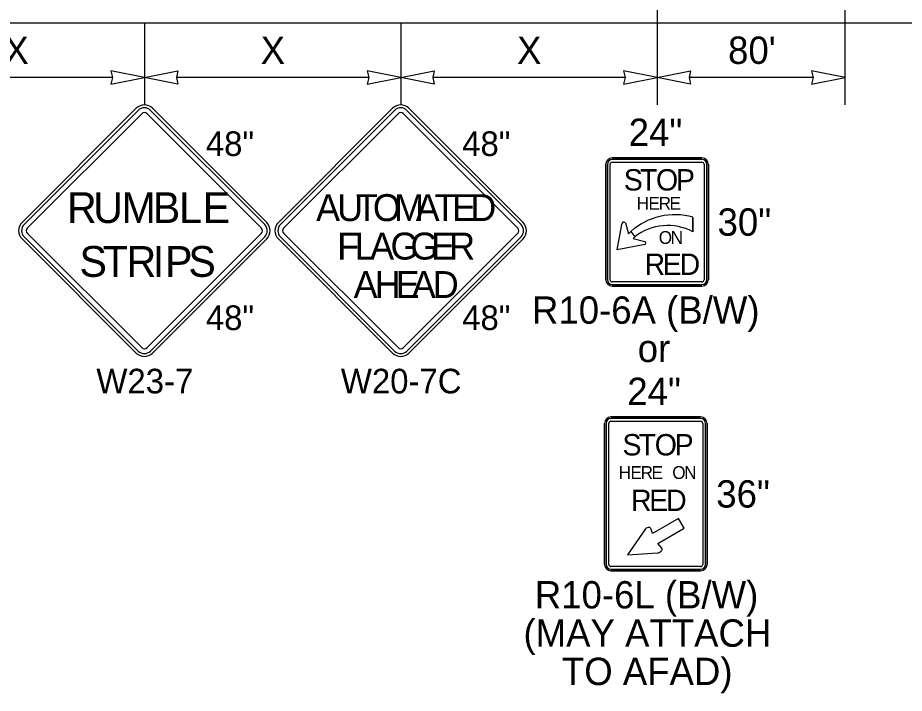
# Model space of a CAD drawing. Extents: x 99999.1 to 100095.7, y 99995 to 100010.7.
# Drawn here: x 100042.406 to 100045, y 100003.772 to 100005.747 of the extents above; entities that cross this region are included whole.
import ezdxf

# ---------------------------------------------------------------- set-up
doc = ezdxf.new("R2010")
doc.units = 0
for name, color, linetype in [('RD_ED_ShoulderPavedEdge', 7, 'Continuous'), ('TR_SN_ConstructionSigns', 7, 'Continuous'), ('TR_WZ_WorkZoneDetails', 7, 'Continuous'), ('TR_WZ_WorkZoneTextCurrent', 7, 'Continuous')]:
    doc.layers.add(name, color=color, linetype=linetype)

msp = doc.modelspace()

# ---------------------------------------------------------------- linework, layer by layer
at = {"layer": 'RD_ED_ShoulderPavedEdge'}
msp.add_line((100040.1076, 100005.7323), (100055.6424, 100005.7323), dxfattribs=at)
at = {"layer": 'TR_SN_ConstructionSigns'}
for p, q in [((100042.7528, 100005.4824), (100042.4187, 100005.1483)), ((100042.7588, 100005.4765), (100042.4246, 100005.1424)), ((100043.1287, 100005.1424), (100042.7945, 100005.4765)), ((100043.1346, 100005.1483), (100042.8005, 100005.4824)), ((100043.5028, 100005.4824), (100043.1687, 100005.1483)), ((100043.5088, 100005.4765), (100043.1746, 100005.1424)), ((100043.8787, 100005.1424), (100043.5445, 100005.4765)), ((100043.8846, 100005.1483), (100043.5505, 100005.4824)), ((100042.4346, 100005.1324), (100042.7687, 100005.4665)), ((100042.7846, 100005.4665), (100043.1187, 100005.1324)), ((100043.1846, 100005.1324), (100043.5187, 100005.4665)), ((100043.5346, 100005.4665), (100043.8687, 100005.1324)), ((100044.1267, 100005.3186), (100044.1267, 100004.9811)), ((100044.1267, 100004.9811), (100044.1267, 100005.3186)), ((100044.1267, 100005.3186), (100044.1267, 100004.9811)), ((100044.1267, 100004.9811), (100044.1267, 100005.3186)), ((100044.1313, 100005.3186), (100044.1313, 100004.9811)), ((100044.1392, 100004.9811), (100044.1392, 100005.3186)), ((100044.4079, 100005.3373), (100044.1454, 100005.3373)), ((100044.1454, 100005.3373), (100044.4079, 100005.3373)), ((100044.4079, 100005.3373), (100044.1454, 100005.3373)), ((100044.1454, 100005.3373), (100044.4079, 100005.3373)), ((100044.4079, 100005.3326), (100044.1454, 100005.3326)), ((100044.1454, 100005.3248), (100044.4079, 100005.3248)), ((100044.4142, 100005.3186), (100044.4142, 100004.9811)), ((100044.422, 100004.9811), (100044.422, 100005.3186)), ((100044.4267, 100004.9811), (100044.4267, 100005.3186)), ((100044.4267, 100005.3186), (100044.4267, 100004.9811)), ((100044.4267, 100004.9811), (100044.4267, 100005.3186)), ((100044.4267, 100005.3186), (100044.4267, 100004.9811)), ((100044.3816, 100005.1635), (100044.3813, 100005.1216)), ((100044.3813, 100005.1216), (100044.3816, 100005.1635)), ((100044.1595, 100005.0686), (100044.1731, 100005.143)), ((100044.1839, 100005.1479), (100044.1933, 100005.1154)), ((100042.7687, 100004.7824), (100042.4346, 100005.1165)), ((100043.1187, 100005.1165), (100042.7846, 100004.7824)), ((100043.5187, 100004.7824), (100043.1846, 100005.1165)), ((100043.8687, 100005.1165), (100043.5346, 100004.7824)), ((100044.1933, 100005.1154), (100044.1996, 100005.1218)), ((100044.1996, 100005.1218), (100044.2113, 100005.1069)), ((100044.1996, 100005.1218), (100044.2113, 100005.1069)), ((100042.4187, 100005.1006), (100042.7528, 100004.7665)), ((100042.4246, 100005.1066), (100042.7588, 100004.7725)), ((100042.7945, 100004.7725), (100043.1287, 100005.1066)), ((100042.8005, 100004.7665), (100043.1346, 100005.1006)), ((100043.1687, 100005.1006), (100043.5028, 100004.7665)), ((100043.1746, 100005.1066), (100043.5088, 100004.7725)), ((100043.5445, 100004.7725), (100043.8787, 100005.1066)), ((100043.5505, 100004.7665), (100043.8846, 100005.1006)), ((100044.2406, 100005.0837), (100044.1595, 100005.0686)), ((100044.2113, 100005.1069), (100044.2066, 100005.1021)), ((100044.2066, 100005.1021), (100044.2408, 100005.0929)), ((100044.4079, 100004.9748), (100044.1454, 100004.9748)), ((100044.1454, 100004.967), (100044.4079, 100004.967)), ((100044.1454, 100004.9623), (100044.4079, 100004.9623)), ((100044.4079, 100004.9623), (100044.1454, 100004.9623)), ((100044.1454, 100004.9623), (100044.4079, 100004.9623)), ((100044.4079, 100004.9623), (100044.1454, 100004.9623)), ((100044.4041, 100004.5796), (100044.1416, 100004.5796)), ((100044.1416, 100004.5796), (100044.4041, 100004.5796)), ((100044.4041, 100004.5796), (100044.1416, 100004.5796)), ((100044.4041, 100004.5749), (100044.1416, 100004.5749)), ((100044.1416, 100004.5671), (100044.4041, 100004.5671)), ((100044.1229, 100004.5609), (100044.1229, 100004.1484)), ((100044.1229, 100004.1484), (100044.1229, 100004.5609)), ((100044.1229, 100004.5609), (100044.1229, 100004.1484)), ((100044.1276, 100004.5609), (100044.1276, 100004.1484)), ((100044.1354, 100004.1484), (100044.1354, 100004.5609)), ((100044.4104, 100004.5609), (100044.4104, 100004.1484)), ((100044.4182, 100004.1484), (100044.4182, 100004.5609)), ((100044.4229, 100004.1484), (100044.4229, 100004.5609)), ((100044.4229, 100004.5609), (100044.4229, 100004.1484)), ((100044.4229, 100004.1484), (100044.4229, 100004.5609)), ((100044.3396, 100004.2827), (100044.263, 100004.2385)), ((100044.356, 100004.2543), (100044.3396, 100004.2827)), ((100044.2786, 100004.2096), (100044.356, 100004.2543)), ((100044.2424, 100004.2523), (100044.1898, 100004.1766)), ((100044.263, 100004.2385), (100044.2592, 100004.2511)), ((100044.2909, 100004.1959), (100044.2786, 100004.2096)), ((100044.1898, 100004.1766), (100044.2776, 100004.1827)), ((100044.4041, 100004.1421), (100044.1416, 100004.1421)), ((100044.1416, 100004.1343), (100044.4041, 100004.1343)), ((100044.1416, 100004.1296), (100044.4041, 100004.1296)), ((100044.4041, 100004.1296), (100044.1416, 100004.1296)), ((100044.1416, 100004.1296), (100044.4041, 100004.1296))]:
    msp.add_line(p, q, dxfattribs=at)
for centre, radius, start, end in [((100042.7767, 100005.4586), 0.0338, 45, 135), ((100042.7767, 100005.4586), 0.0253, 45, 135), ((100043.5267, 100005.4586), 0.0338, 45, 135), ((100043.5267, 100005.4586), 0.0253, 45, 135), ((100042.7767, 100005.4586), 0.0113, 45, 135), ((100043.5267, 100005.4586), 0.0113, 45, 135), ((100044.1454, 100005.3186), 0.0187, 90, 180), ((100044.1454, 100005.3186), 0.0187, 90, 180), ((100044.1454, 100005.3186), 0.0187, 90, 180), ((100044.1454, 100005.3186), 0.0187, 90, 180), ((100044.1454, 100005.3186), 0.0141, 90, 180), ((100044.1454, 100005.3186), 0.00625, 90, 180), ((100044.4079, 100005.3186), 0.0187, 0, 90), ((100044.4079, 100005.3186), 0.0187, 0, 90), ((100044.4079, 100005.3186), 0.0187, 0, 90), ((100044.4079, 100005.3186), 0.0187, 0, 90), ((100044.4079, 100005.3186), 0.0141, 0, 90), ((100044.4079, 100005.3186), 0.00625, 0, 90), ((100044.3279, 100004.9804), 0.1909, 73.6434, 132.2131), ((100044.3279, 100004.9804), 0.1909, 73.6434, 132.2131), ((100042.4425, 100005.1245), 0.0338, 135, 225), ((100042.4425, 100005.1245), 0.0253, 135, 225), ((100043.1108, 100005.1245), 0.0253, 315, 45), ((100043.1108, 100005.1245), 0.0338, 315, 45), ((100043.1925, 100005.1245), 0.0338, 135, 225), ((100043.1925, 100005.1245), 0.0253, 135, 225), ((100043.8608, 100005.1245), 0.0253, 315, 45), ((100043.8608, 100005.1245), 0.0338, 315, 45), ((100044.3078, 100004.981), 0.1586, 62.4149, 127.4769), ((100044.3078, 100004.981), 0.1586, 62.4149, 127.4769), ((100042.4425, 100005.1245), 0.0113, 135, 225), ((100043.1108, 100005.1245), 0.0113, 315, 45), ((100043.1925, 100005.1245), 0.0113, 135, 225), ((100043.8608, 100005.1245), 0.0113, 315, 45), ((100044.1454, 100004.9811), 0.0187, 180, 270), ((100044.1454, 100004.9811), 0.0187, 180, 270), ((100044.1454, 100004.9811), 0.0187, 180, 270), ((100044.1454, 100004.9811), 0.0187, 180, 270), ((100044.1454, 100004.9811), 0.0141, 180, 270), ((100044.1454, 100004.9811), 0.00625, 180, 270), ((100044.4079, 100004.9811), 0.0187, 270, 0), ((100044.4079, 100004.9811), 0.0187, 270, 0), ((100044.4079, 100004.9811), 0.0187, 270, 0), ((100044.4079, 100004.9811), 0.0141, 270, 0), ((100044.4079, 100004.9811), 0.00625, 270, 0), ((100044.4079, 100004.9811), 0.0187, 270, 0), ((100042.7767, 100004.7904), 0.0253, 225, 315), ((100042.7767, 100004.7904), 0.0113, 225, 315), ((100043.5267, 100004.7904), 0.0253, 225, 315), ((100043.5267, 100004.7904), 0.0113, 225, 315), ((100042.7767, 100004.7904), 0.0338, 225, 315), ((100043.5267, 100004.7904), 0.0338, 225, 315), ((100044.1416, 100004.5609), 0.0187, 90, 180), ((100044.1416, 100004.5609), 0.0187, 90, 180), ((100044.1416, 100004.5609), 0.0187, 90, 180), ((100044.1416, 100004.5609), 0.0141, 90, 180), ((100044.1416, 100004.5609), 0.00625, 90, 180), ((100044.4041, 100004.5609), 0.0187, 0, 90), ((100044.4041, 100004.5609), 0.0187, 0, 90), ((100044.4041, 100004.5609), 0.0187, 0, 90), ((100044.4041, 100004.5609), 0.0141, 0, 90), ((100044.4041, 100004.5609), 0.00625, 0, 90), ((100044.1416, 100004.1484), 0.0187, 180, 270), ((100044.1416, 100004.1484), 0.0187, 180, 270), ((100044.1416, 100004.1484), 0.0187, 180, 270), ((100044.1416, 100004.1484), 0.0141, 180, 270), ((100044.1416, 100004.1484), 0.00625, 180, 270), ((100044.4041, 100004.1484), 0.0187, 270, 0), ((100044.4041, 100004.1484), 0.0187, 270, 0), ((100044.4041, 100004.1484), 0.0187, 270, 0), ((100044.4041, 100004.1484), 0.0141, 270, 0), ((100044.4041, 100004.1484), 0.00625, 270, 0)]:
    msp.add_arc(centre, radius, start, end, dxfattribs=at)
for centre, major_axis, ratio, start_param, end_param in [((100044.1795, 100005.1431), (-0.00647, -0.00009), 0.989437, 3.962549, 6.283185), ((100044.2384, 100005.0883), (-0.0046, 0.00239), 0.999053, 2.490568, 4.712389), ((100044.2492, 100004.248), (0.00934, 0.00539), 0.700347, 5.977036, 8.198856), ((100044.2816, 100004.1909), (-0.00913, -0.00527), 0.700347, 0.771965, 3.092601)]:
    msp.add_ellipse(centre, major_axis=major_axis, ratio=ratio, start_param=start_param, end_param=end_param, dxfattribs=at)
at = {"layer": 'TR_WZ_WorkZoneDetails'}
for p, q in [((100044.2767, 100008.7991), (100044.2767, 100005.4923)), ((100044.8267, 100005.4923), (100044.8267, 100007.7323)), ((100042.7767, 100005.7323), (100042.7767, 100005.4923)), ((100043.5267, 100005.7323), (100043.5267, 100005.4923)), ((100042.6829, 100005.5723), (100042.1204, 100005.5723)), ((100043.4329, 100005.5723), (100042.8704, 100005.5723)), ((100044.1829, 100005.5723), (100043.6204, 100005.5723)), ((100044.7329, 100005.5723), (100044.3704, 100005.5723))]:
    msp.add_line(p, q, dxfattribs=at)
for points in [[(100042.7767, 100005.5723), (100042.6784, 100005.5916), (100042.6829, 100005.5723), (100042.6784, 100005.5531)], [(100042.7767, 100005.5723), (100042.8749, 100005.5916), (100042.8704, 100005.5723), (100042.8749, 100005.5531)], [(100043.5267, 100005.5723), (100043.4284, 100005.5916), (100043.4329, 100005.5723), (100043.4284, 100005.5531)], [(100043.5267, 100005.5723), (100043.6249, 100005.5916), (100043.6204, 100005.5723), (100043.6249, 100005.5531)], [(100044.2767, 100005.5723), (100044.1784, 100005.5916), (100044.1829, 100005.5723), (100044.1784, 100005.5531)], [(100044.2767, 100005.5723), (100044.3749, 100005.5916), (100044.3704, 100005.5723), (100044.3749, 100005.5531)], [(100044.8267, 100005.5723), (100044.7284, 100005.5916), (100044.7329, 100005.5723), (100044.7284, 100005.5531)]]:
    msp.add_lwpolyline(points, close=True, dxfattribs=at)

# ---------------------------------------------------------------- texts
at = {"layer": 'TR_SN_ConstructionSigns'}
for s, height, p in [('24"', 0.08, (100044.1936, 100005.3723)), ('48"', 0.072, (100042.9564, 100005.343)), ('48"', 0.072, (100043.7064, 100005.343)), ('30"', 0.08, (100044.4536, 100005.1098)), ('R10-6A (B/W)', 0.08, (100043.9107, 100004.8523)), ('48"', 0.072, (100042.9564, 100004.8339)), ('48"', 0.072, (100043.7064, 100004.8339)), ('or', 0.08, (100044.2201, 100004.7403)), ('W23-7', 0.072, (100042.6361, 100004.6486)), ('W20-7C', 0.072, (100043.3514, 100004.6486)), ('24"', 0.08, (100044.1895, 100004.6146)), ('36"', 0.08, (100044.4498, 100004.3146)), ('R10-6L (B/W)', 0.08, (100043.919, 100004.0196)), ('(MAY ATTACH', 0.08, (100043.8858, 100003.9076)), ('TO AFAD)', 0.08, (100043.9982, 100003.7956))]:
    msp.add_text(s, height=height, rotation=360, dxfattribs=at).set_placement(p)
for s, height, p in [('S', 0.0625, (100044.1792, 100005.242)), ('T', 0.0625, (100044.2267, 100005.242)), ('O', 0.0625, (100044.2735, 100005.242)), ('P', 0.0625, (100044.3317, 100005.242)), ('R', 0.09, (100042.5503, 100005.147)), ('U', 0.09, (100042.6268, 100005.147)), ('M', 0.09, (100042.7096, 100005.147)), ('B', 0.09, (100042.8014, 100005.147)), ('L', 0.09, (100042.8779, 100005.147)), ('E', 0.09, (100042.9472, 100005.147)), ('A', 0.0787, (100043.279, 100005.1526)), ('U', 0.0787, (100043.3404, 100005.1526)), ('T', 0.0787, (100043.3955, 100005.1526)), ('O', 0.0787, (100043.4451, 100005.1526)), ('M', 0.0787, (100043.5074, 100005.1526)), ('A', 0.0787, (100043.5704, 100005.1526)), ('T', 0.0787, (100043.6255, 100005.1526)), ('E', 0.0787, (100043.6767, 100005.1526)), ('D', 0.0787, (100043.7302, 100005.1526)), ('H', 0.0375, (100044.217, 100005.1858)), ('E', 0.0375, (100044.2515, 100005.1858)), ('R', 0.0375, (100044.2812, 100005.1858)), ('E', 0.0375, (100044.313, 100005.1858)), ('F', 0.0787, (100043.3408, 100005.0401)), ('L', 0.0787, (100043.392, 100005.0401)), ('A', 0.0787, (100043.4369, 100005.0401)), ('G', 0.0787, (100043.4967, 100005.0401)), ('G', 0.0787, (100043.555, 100005.0401)), ('E', 0.0787, (100043.6149, 100005.0401)), ('R', 0.0787, (100043.6684, 100005.0401)), ('O', 0.0375, (100044.2815, 100005.0858)), ('N', 0.0375, (100044.3164, 100005.0858)), ('S', 0.09, (100042.5868, 100004.9895)), ('T', 0.09, (100042.6552, 100004.9895)), ('R', 0.09, (100042.7245, 100004.9895)), ('I', 0.09, (100042.801, 100004.9895)), ('P', 0.09, (100042.837, 100004.9895)), ('S', 0.09, (100042.9054, 100004.9895)), ('R', 0.0625, (100044.2399, 100004.9951)), ('E', 0.0625, (100044.293, 100004.9951)), ('D', 0.0625, (100044.3424, 100004.9951)), ('A', 0.0787, (100043.3888, 100004.9276)), ('H', 0.0787, (100043.4503, 100004.9276)), ('E', 0.0787, (100043.5117, 100004.9276)), ('A', 0.0787, (100043.5589, 100004.9276)), ('D', 0.0787, (100043.6204, 100004.9276)), ('S', 0.0625, (100044.1754, 100004.4671)), ('T', 0.0625, (100044.2229, 100004.4671)), ('O', 0.0625, (100044.2698, 100004.4671)), ('P', 0.0625, (100044.3279, 100004.4671)), ('H', 0.0375, (100044.1643, 100004.3984)), ('E', 0.0375, (100044.1988, 100004.3984)), ('R', 0.0375, (100044.2284, 100004.3984)), ('E', 0.0375, (100044.2603, 100004.3984)), ('O', 0.0375, (100044.3211, 100004.3984)), ('N', 0.0375, (100044.3559, 100004.3984)), ('R', 0.0625, (100044.2004, 100004.3046)), ('E', 0.0625, (100044.2535, 100004.3046)), ('D', 0.0625, (100044.3029, 100004.3046))]:
    msp.add_text(s, height=height, dxfattribs=at).set_placement(p)
at = {"layer": 'TR_WZ_WorkZoneTextCurrent'}
for s, p in [('X', (100042.3669, 100005.6123)), ('X', (100043.1169, 100005.6123)), ('X', (100043.8669, 100005.6123)), ("80'", (100044.4844, 100005.6123))]:
    msp.add_text(s, height=0.08, rotation=360, dxfattribs=at).set_placement(p)

doc.saveas('drawing.dxf')
